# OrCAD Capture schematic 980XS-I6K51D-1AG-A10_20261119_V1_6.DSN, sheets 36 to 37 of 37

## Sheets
36 P0062_S6_USB/AUD/FLASH/XTAL: size A1
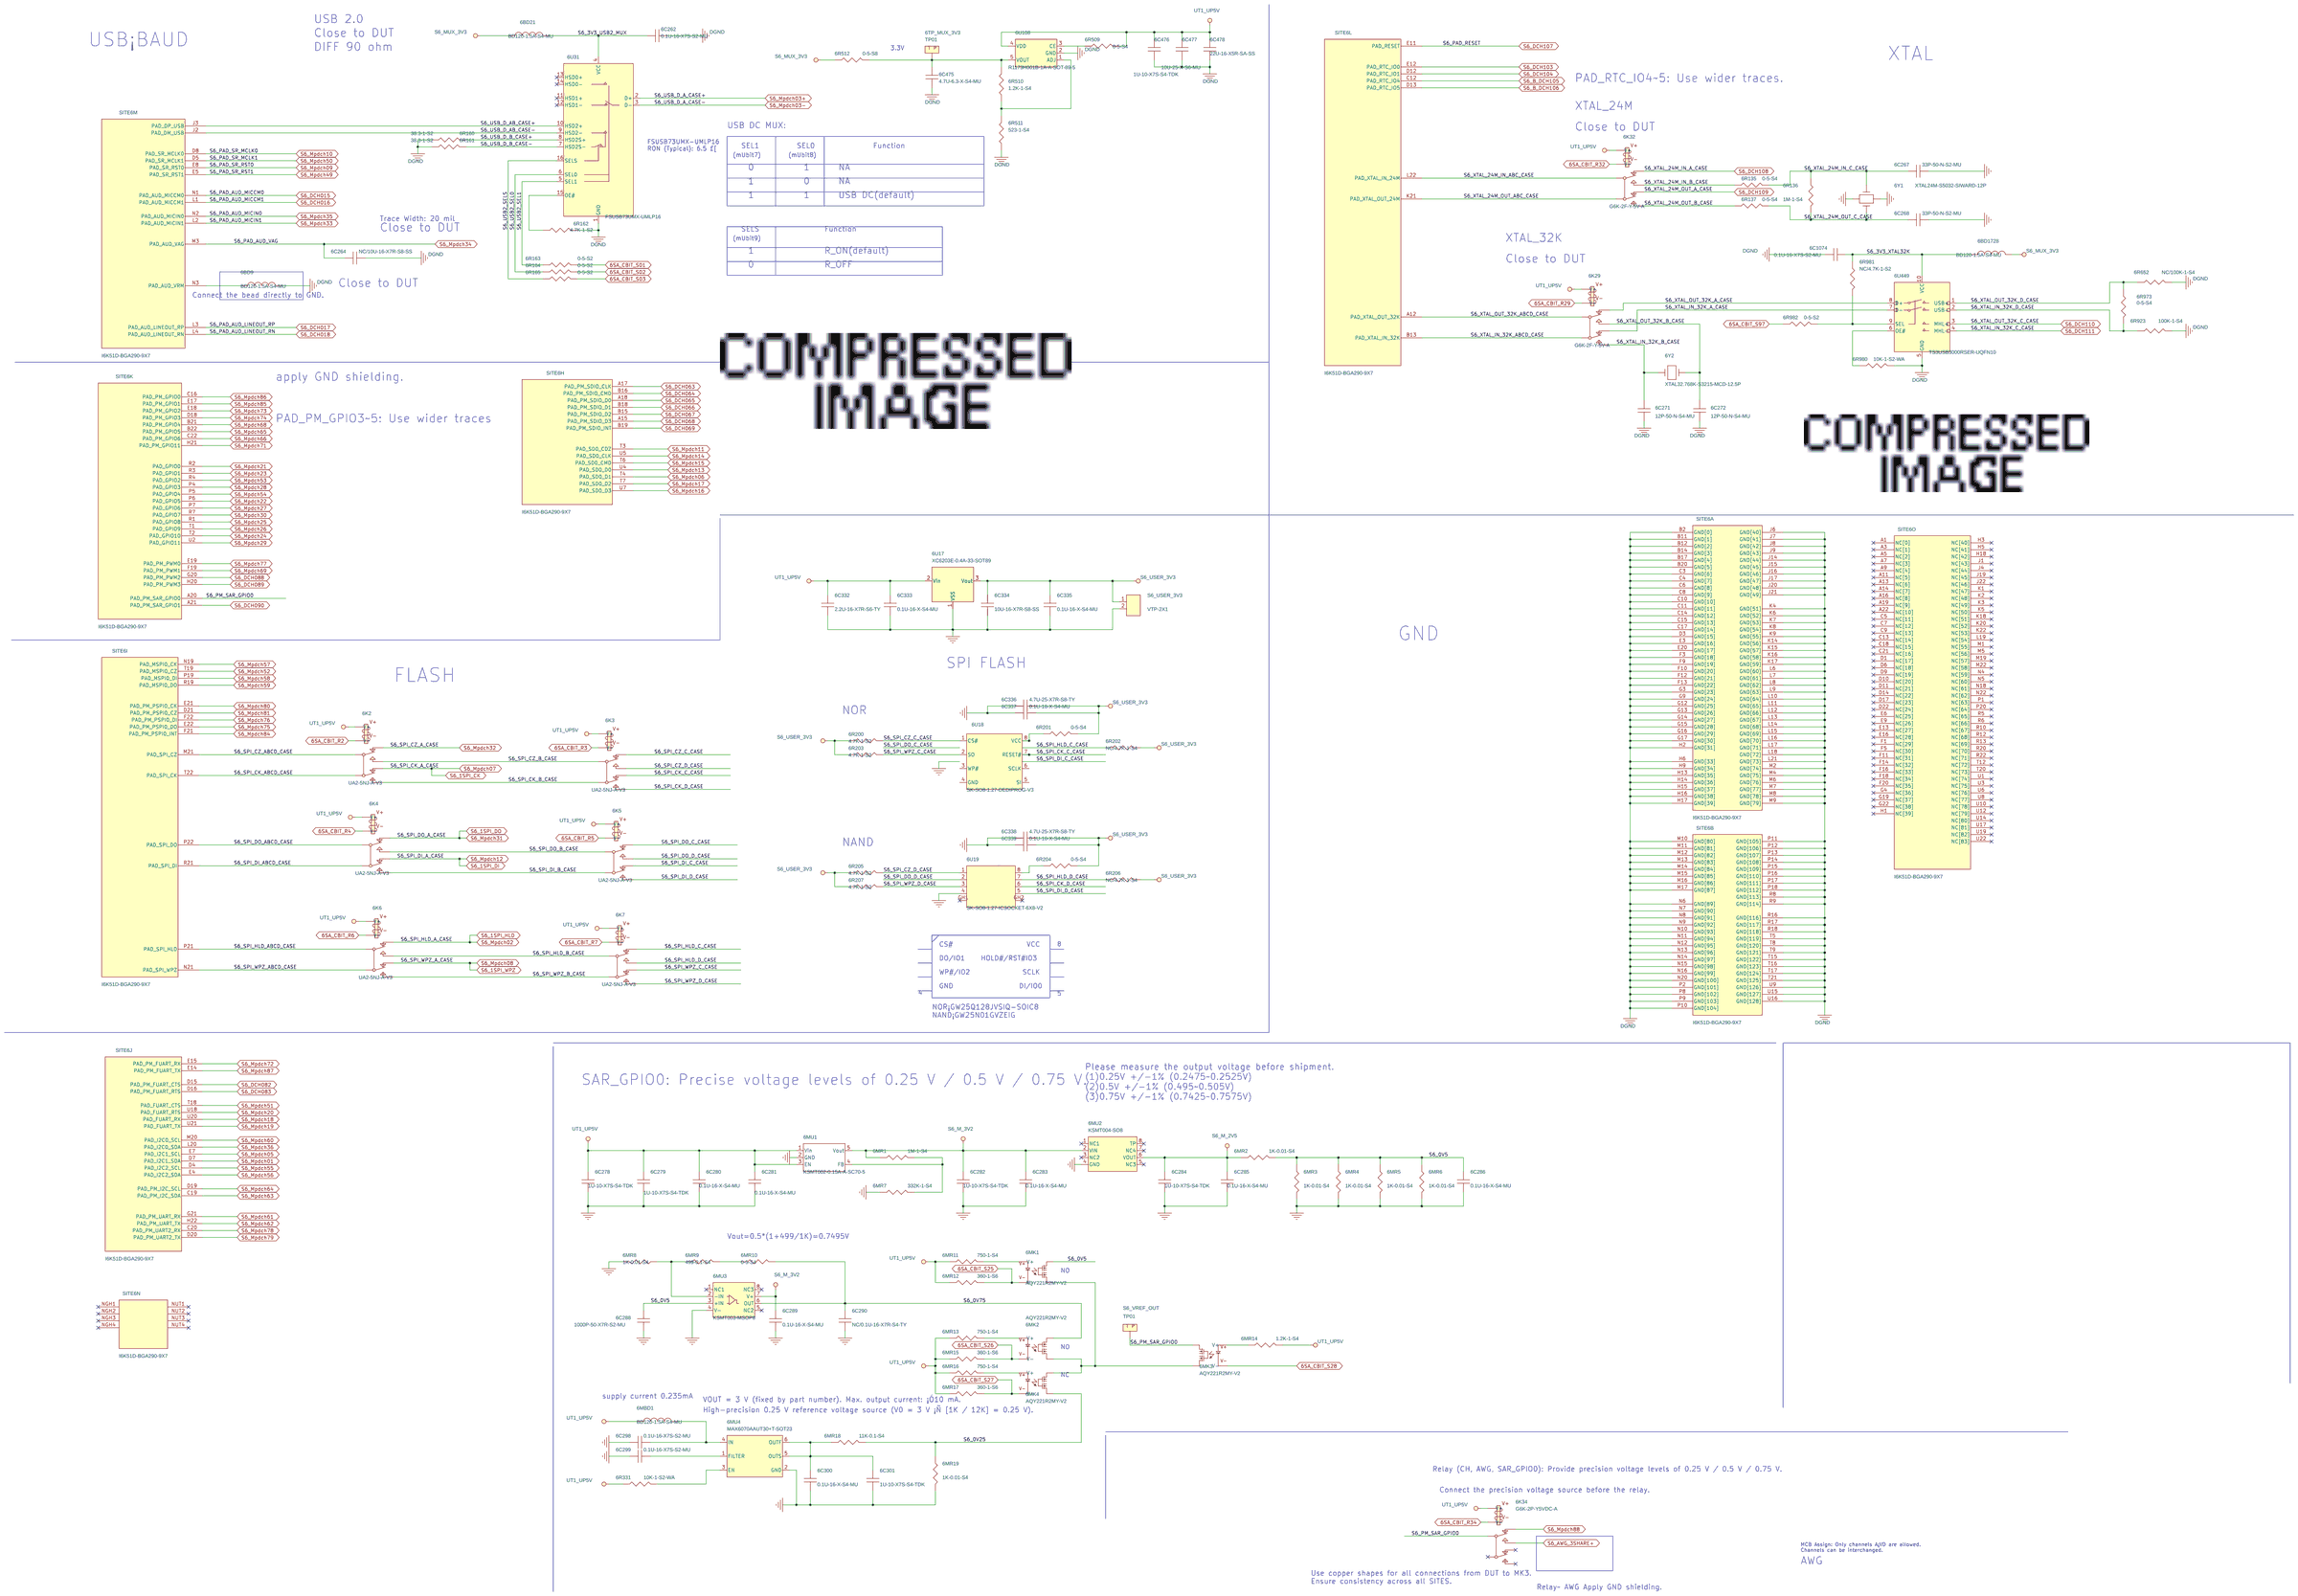
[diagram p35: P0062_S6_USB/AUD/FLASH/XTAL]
37 P0082_S8_USB/AUD/FLASH/XTAL: size A1
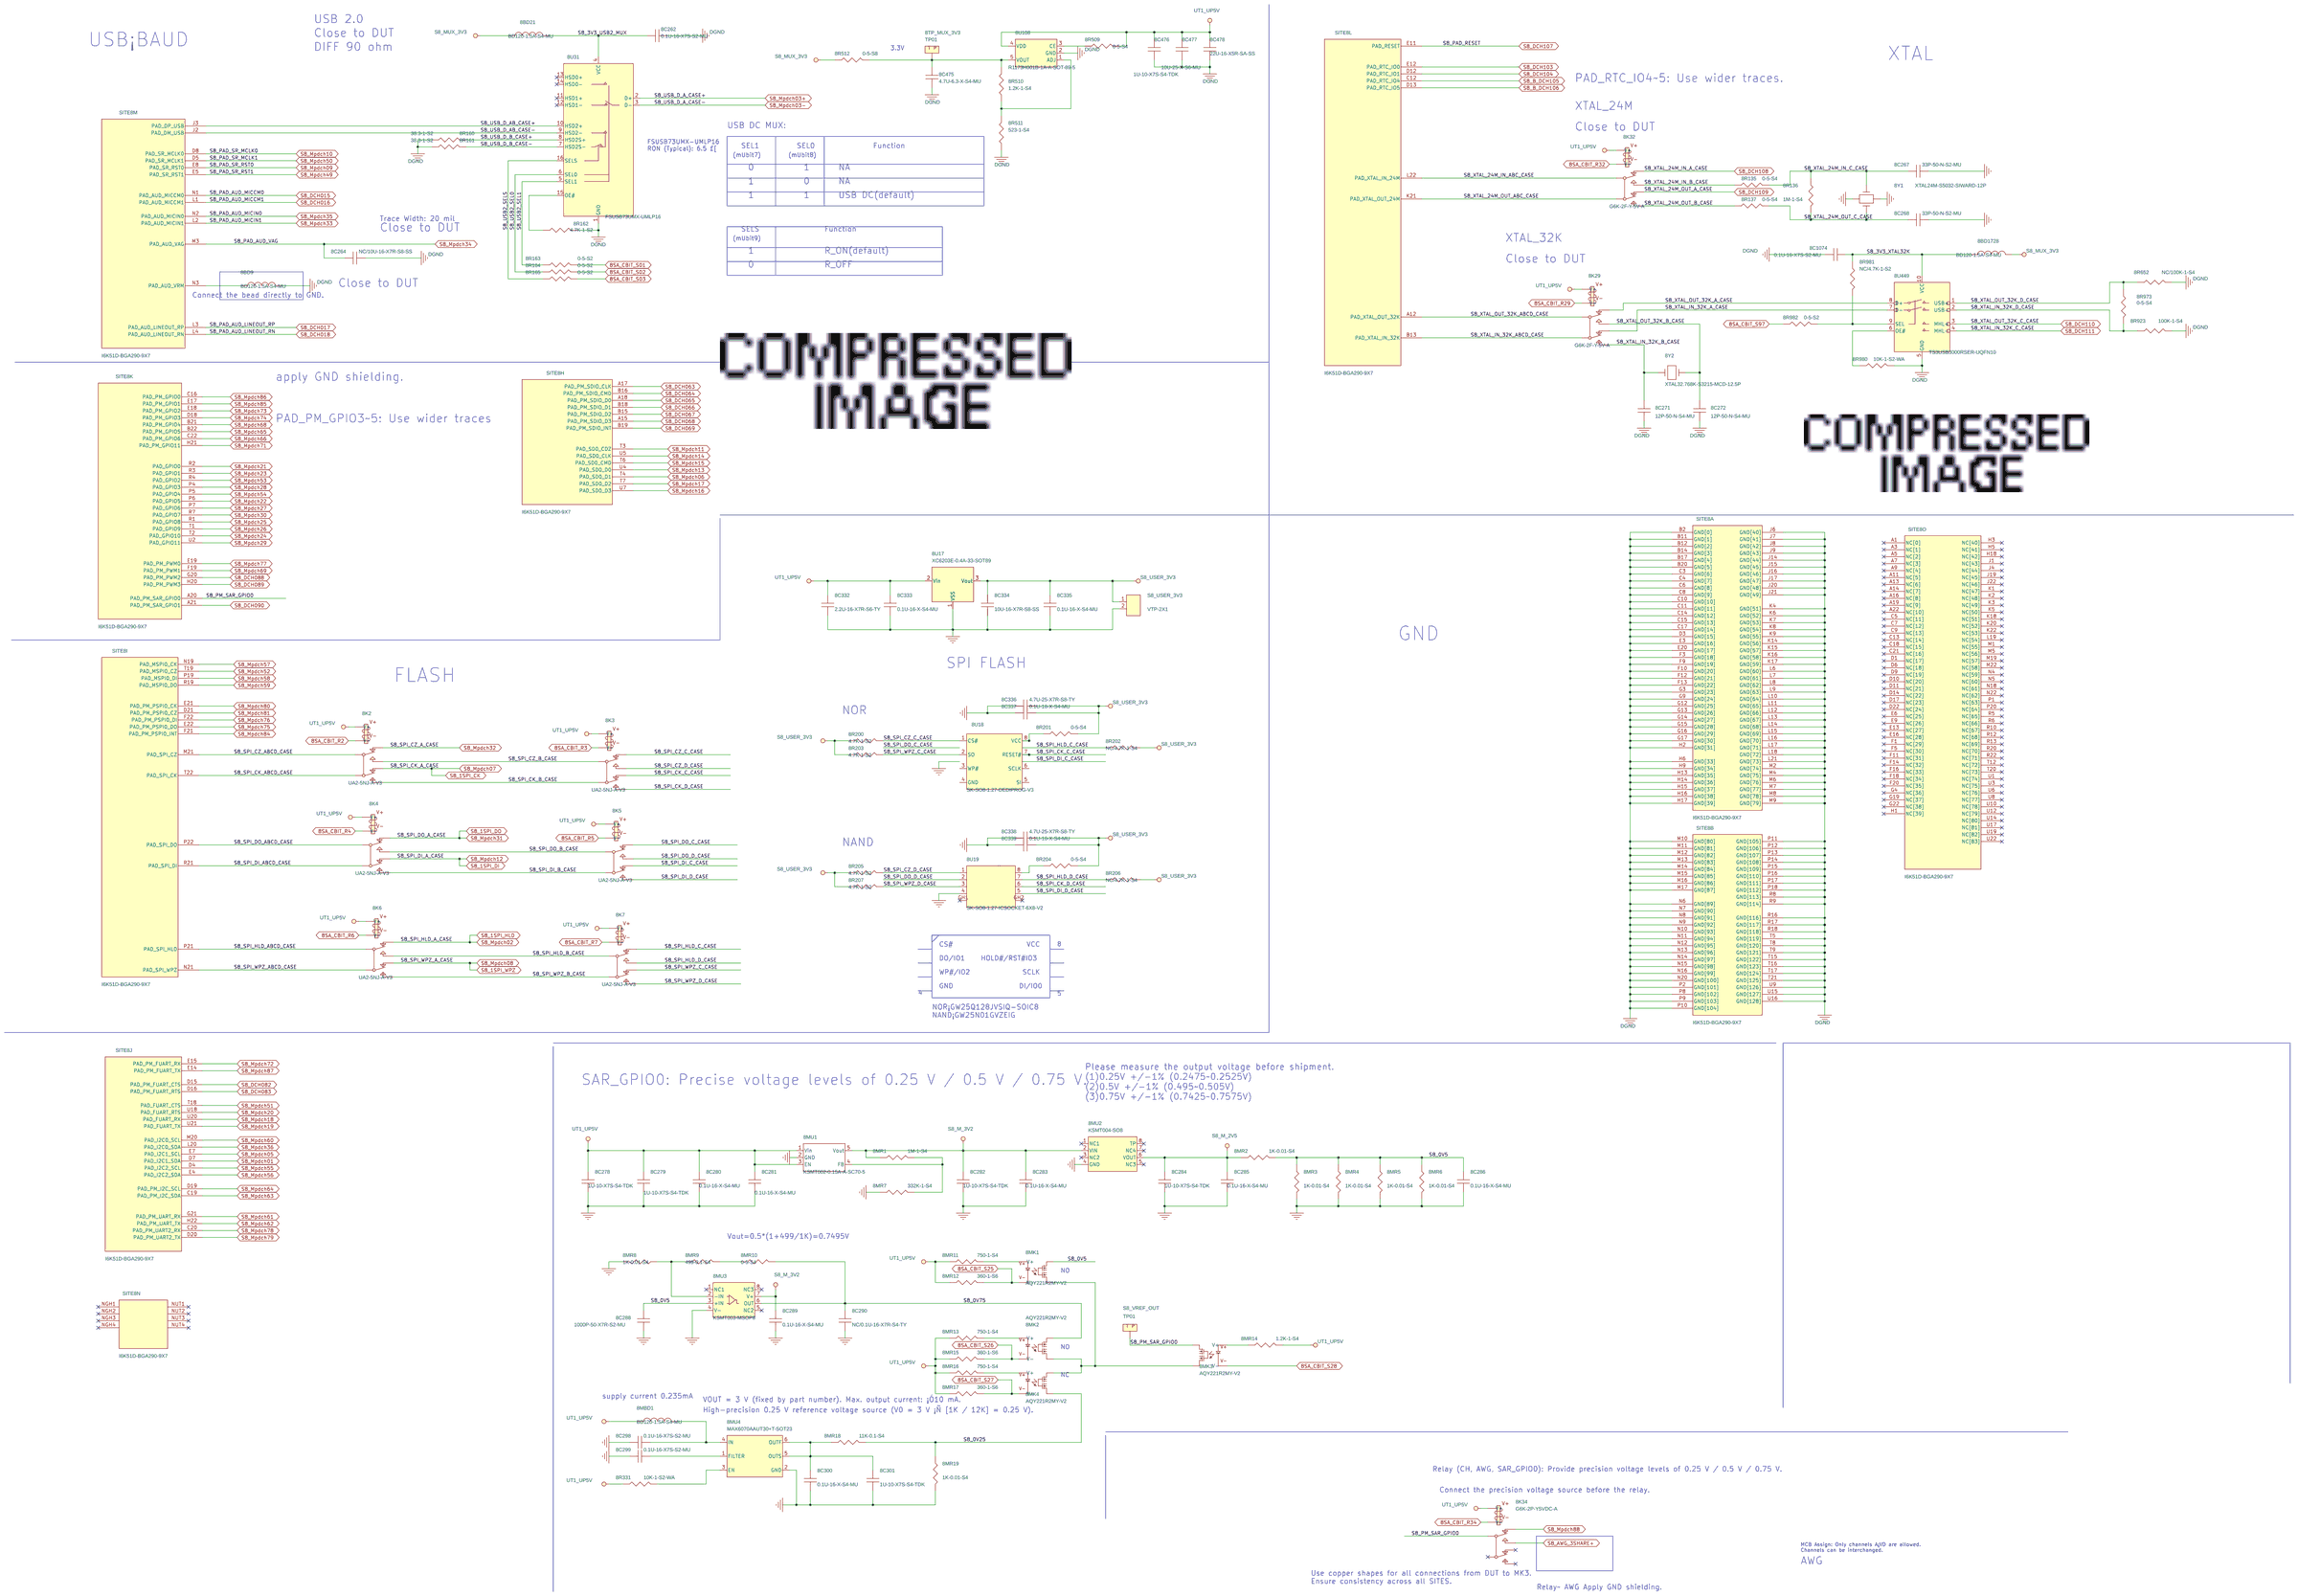
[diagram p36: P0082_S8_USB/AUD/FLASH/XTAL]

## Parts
sheet P0062_S6_USB/AUD/FLASH/XTAL
6BD9  BD120-1.5A-S4-MU  [FB0402]
6BD21  BD120-1.5A-S4-MU  [FB0402]
6BD1728  BD120-1.5A-S4-MU  [FB0402]
6C262  0.1U-16-X7S-S2-MU  [C0201]
6C264  NC/10U-16-X7R-S8-SS  [C0805]
6C267  33P-50-N-S2-MU  [C0201]
6C268  33P-50-N-S2-MU  [C0201]
6C271  12P-50-N-S4-MU  [C0402]
6C272  12P-50-N-S4-MU  [C0402]
6C278  1U-10-X7S-S4-TDK  [C0402]
6C279  1U-10-X7S-S4-TDK  [C0402]
6C280  0.1U-16-X-S4-MU  [C0402]
6C281  0.1U-16-X-S4-MU  [C0402]
6C282  1U-10-X7S-S4-TDK  [C0402]
6C283  0.1U-16-X-S4-MU  [C0402]
6C284  1U-10-X7S-S4-TDK  [C0402]
6C285  0.1U-16-X-S4-MU  [C0402]
6C286  0.1U-16-X-S4-MU  [C0402]
6C288  1000P-50-X7R-S2-MU  [C0201]
6C289  0.1U-16-X-S4-MU  [C0402]
6C290  NC/0.1U-16-X7R-S4-TY  [C0402]
6C298  0.1U-16-X7S-S2-MU  [C0201]
6C299  0.1U-16-X7S-S2-MU  [C0201]
6C300  0.1U-16-X-S4-MU  [C0402]
6C301  1U-10-X7S-S4-TDK  [C0402]
6C332  2.2U-16-X7R-S6-TY  [C0603]
6C333  0.1U-16-X-S4-MU  [C0402]
6C334  10U-16-X7R-S8-SS  [C0805]
6C335  0.1U-16-X-S4-MU  [C0402]
6C336  4.7U-25-X7R-S8-TY  [C0805]
6C337  0.1U-16-X-S4-MU  [C0402]
6C338  4.7U-25-X7R-S8-TY  [C0805]
6C339  0.1U-16-X-S4-MU  [C0402]
6C475  4.7U-6.3-X-S4-MU  [C0402]
6C476  1U-10-X7S-S4-TDK  [C0402]
6C477  10U-25-X-S6-MU  [C0603]
6C478  22U-16-X5R-SA-SS  [C1206]
6C1074  0.1U-16-X7S-S2-MU  [C0201_MINI]
6K2  UA2-5NJ-A-V3  [RL_NECUA2_5V_V3]
6K3  UA2-5NJ-A-V3  [RL_NECUA2_5V_V3]
6K4  UA2-5NJ-A-V3  [RL_NECUA2_5V_V3]
6K5  UA2-5NJ-A-V3  [RL_NECUA2_5V_V3]
6K6  UA2-5NJ-A-V3  [RL_NECUA2_5V_V3]
6K7  UA2-5NJ-A-V3  [RL_NECUA2_5V_V3]
6K29  G6K-2F-Y-5V-A  [RL_G6K2F-Y_5V_OMRON]
6K32  G6K-2F-Y-5V-A  [RL_G6K2F-Y_5V_OMRON]
6K34  G6K-2P-Y5VDC-A  [RL_OMRONG6K2PY_5V]
6MBD1  BD120-1.5A-S4-MU  [FB0402]
6MK1  AQY221R2MY-V2  [RL_AQY221R2MY_5V_V2]
6MK2  AQY221R2MY-V2  [RL_AQY221R2MY_5V_V2]
6MK3  AQY221R2MY-V2  [RL_AQY221R2MY_5V_V2]
6MK4  AQY221R2MY-V2  [RL_AQY221R2MY_5V_V2]
6MR1  1M-1-S4  [R0402_UNBGA_V2]
6MR2  1K-0.01-S4  [R0402_UNBGA_V2]
6MR3  1K-0.01-S4  [R0402_UNBGA_V2]
6MR4  1K-0.01-S4  [R0402_UNBGA_V2]
6MR5  1K-0.01-S4  [R0402_UNBGA_V2]
6MR6  1K-0.01-S4  [R0402_UNBGA_V2]
6MR7  332K-1-S4  [R0402_UNBGA_V2]
6MR8  1K-0.01-S4  [R0402_UNBGA_V2]
6MR9  499-0.1-S4  [R0402]
6MR10  0-5-S4  [R0402]
6MR11  750-1-S4  [R0402]
6MR12  360-1-S6  [R0603]
6MR13  750-1-S4  [R0402]
6MR14  1.2K-1-S4  [R0402]
6MR15  360-1-S6  [R0603]
6MR16  750-1-S4  [R0402]
6MR17  360-1-S6  [R0603]
6MR18  11K-0.1-S4  [R0402]
6MR19  1K-0.01-S4  [R0402_UNBGA_V2]
6MU1  KSMT002-0.15A-A-SC70-5  [SC70_5P]
6MU2  KSMT004-SO8  [SO8_244X127MM]
6MU3  KSMT003-MSOP8  [SO8_172X0P65MM]
6MU4  MAX6070AAUT30+T-SOT23  [SOT23_6P_0P95X2P7MM_H1P45MM]
6R135  0-5-S4  [R0402]
6R136  1M-1-S4  [R0402]
6R137  0-5-S4  [R0402]
6R160  38.3-1-S2  [R0201_MINI]
6R161  38.3-1-S2  [R0201_MINI]
6R162  4.7K-1-S2  [R0201_MINI]
6R163  0-5-S2  [R0201_MINI]
6R164  0-5-S2  [R0201_MINI]
6R165  0-5-S2  [R0201_MINI]
6R200  4.7K-1-S2  [R0201]
6R201  0-5-S4  [R0402]
6R202  NC/4.7K-1-S4  [R0402]
6R203  4.7K-1-S2  [R0201]
6R204  0-5-S4  [R0402]
6R205  4.7K-1-S2  [R0201]
6R206  NC/4.7K-1-S4  [R0402]
6R207  4.7K-1-S2  [R0201]
6R331  10K-1-S2-WA  [R0201]
6R509  0-5-S4  [R0402]
6R510  1.2K-1-S4  [R0402]
6R511  523-1-S4  [R0402]
6R512  0-5-S8  [R0805]
6R652  NC/100K-1-S4  [R0402]
6R923  100K-1-S4  [R0402]
6R973  0-5-S4  [R0402]
6R980  10K-1-S2-WA  [R0201]
6R981  NC/4.7K-1-S2  [R0201]
6R982  0-5-S2  [R0201]
6TP_MUX_3V3  TP01  [TP_040_T]
6U17  XC6203E-0.4A-33-SOT89  [SOT89]
6U18  SK-SO8-1.27-DEDIPROG-V3  [SK_SO8_1P27MM_DEDIPROG_V3]
6U19  SK-SO8-1.27-ICSOCKET-6X8-V2  [SK_SO8_1P27MM_SDQ54CBAA_V2]
6U31  FSUSB73UMX-UMLP16  [SW_UMLP2P6X1P8_12P_0P4MM]
6U108  R1173H001B-1A-A-SOT-89-5  [SOT_89_5]
6U449  TS3USB3000RSER-UQFN10  [UQFN2P05X1P55_10P_0P5MM]
6Y1  XTAL24M-S5032-SIWARD-12P  [XTAL_S_DUAL1]
6Y2  XTAL32.768K-S3215-MCD-12.5P  [XTAL_3P2X1P5MM_2P_MC]
S6_USER_3V3  VTP-2X1  [VTP_2P_100]
S6_VREF_OUT  TP01  [TP_040_T]
SITE6  I6K51D-BGA290-9X7  [SK_TFBGA7X9_290P_0P4MM_JG]  (sections A,B,C,D,E,F,G,H,I,J,K,L,M,N,O)
sheet P0082_S8_USB/AUD/FLASH/XTAL
8BD9  BD120-1.5A-S4-MU  [FB0402]
8BD21  BD120-1.5A-S4-MU  [FB0402]
8BD1728  BD120-1.5A-S4-MU  [FB0402]
8C262  0.1U-16-X7S-S2-MU  [C0201]
8C264  NC/10U-16-X7R-S8-SS  [C0805]
8C267  33P-50-N-S2-MU  [C0201]
8C268  33P-50-N-S2-MU  [C0201]
8C271  12P-50-N-S4-MU  [C0402]
8C272  12P-50-N-S4-MU  [C0402]
8C278  1U-10-X7S-S4-TDK  [C0402]
8C279  1U-10-X7S-S4-TDK  [C0402]
8C280  0.1U-16-X-S4-MU  [C0402]
8C281  0.1U-16-X-S4-MU  [C0402]
8C282  1U-10-X7S-S4-TDK  [C0402]
8C283  0.1U-16-X-S4-MU  [C0402]
8C284  1U-10-X7S-S4-TDK  [C0402]
8C285  0.1U-16-X-S4-MU  [C0402]
8C286  0.1U-16-X-S4-MU  [C0402]
8C288  1000P-50-X7R-S2-MU  [C0201]
8C289  0.1U-16-X-S4-MU  [C0402]
8C290  NC/0.1U-16-X7R-S4-TY  [C0402]
8C298  0.1U-16-X7S-S2-MU  [C0201]
8C299  0.1U-16-X7S-S2-MU  [C0201]
8C300  0.1U-16-X-S4-MU  [C0402]
8C301  1U-10-X7S-S4-TDK  [C0402]
8C332  2.2U-16-X7R-S6-TY  [C0603]
8C333  0.1U-16-X-S4-MU  [C0402]
8C334  10U-16-X7R-S8-SS  [C0805]
8C335  0.1U-16-X-S4-MU  [C0402]
8C336  4.7U-25-X7R-S8-TY  [C0805]
8C337  0.1U-16-X-S4-MU  [C0402]
8C338  4.7U-25-X7R-S8-TY  [C0805]
8C339  0.1U-16-X-S4-MU  [C0402]
8C475  4.7U-6.3-X-S4-MU  [C0402]
8C476  1U-10-X7S-S4-TDK  [C0402]
8C477  10U-25-X-S6-MU  [C0603]
8C478  22U-16-X5R-SA-SS  [C1206]
8C1074  0.1U-16-X7S-S2-MU  [C0201_MINI]
8K2  UA2-5NJ-A-V3  [RL_NECUA2_5V_V3]
8K3  UA2-5NJ-A-V3  [RL_NECUA2_5V_V3]
8K4  UA2-5NJ-A-V3  [RL_NECUA2_5V_V3]
8K5  UA2-5NJ-A-V3  [RL_NECUA2_5V_V3]
8K6  UA2-5NJ-A-V3  [RL_NECUA2_5V_V3]
8K7  UA2-5NJ-A-V3  [RL_NECUA2_5V_V3]
8K29  G6K-2F-Y-5V-A  [RL_G6K2F-Y_5V_OMRON]
8K32  G6K-2F-Y-5V-A  [RL_G6K2F-Y_5V_OMRON]
8K34  G6K-2P-Y5VDC-A  [RL_OMRONG6K2PY_5V]
8MBD1  BD120-1.5A-S4-MU  [FB0402]
8MK1  AQY221R2MY-V2  [RL_AQY221R2MY_5V_V2]
8MK2  AQY221R2MY-V2  [RL_AQY221R2MY_5V_V2]
8MK3  AQY221R2MY-V2  [RL_AQY221R2MY_5V_V2]
8MK4  AQY221R2MY-V2  [RL_AQY221R2MY_5V_V2]
8MR1  1M-1-S4  [R0402_UNBGA_V2]
8MR2  1K-0.01-S4  [R0402_UNBGA_V2]
8MR3  1K-0.01-S4  [R0402_UNBGA_V2]
8MR4  1K-0.01-S4  [R0402_UNBGA_V2]
8MR5  1K-0.01-S4  [R0402_UNBGA_V2]
8MR6  1K-0.01-S4  [R0402_UNBGA_V2]
8MR7  332K-1-S4  [R0402_UNBGA_V2]
8MR8  1K-0.01-S4  [R0402_UNBGA_V2]
8MR9  499-0.1-S4  [R0402]
8MR10  0-5-S4  [R0402]
8MR11  750-1-S4  [R0402]
8MR12  360-1-S6  [R0603]
8MR13  750-1-S4  [R0402]
8MR14  1.2K-1-S4  [R0402]
8MR15  360-1-S6  [R0603]
8MR16  750-1-S4  [R0402]
8MR17  360-1-S6  [R0603]
8MR18  11K-0.1-S4  [R0402]
8MR19  1K-0.01-S4  [R0402_UNBGA_V2]
8MU1  KSMT002-0.15A-A-SC70-5  [SC70_5P]
8MU2  KSMT004-SO8  [SO8_244X127MM]
8MU3  KSMT003-MSOP8  [SO8_172X0P65MM]
8MU4  MAX6070AAUT30+T-SOT23  [SOT23_6P_0P95X2P7MM_H1P45MM]
8R135  0-5-S4  [R0402]
8R136  1M-1-S4  [R0402]
8R137  0-5-S4  [R0402]
8R160  38.3-1-S2  [R0201_MINI]
8R161  38.3-1-S2  [R0201_MINI]
8R162  4.7K-1-S2  [R0201_MINI]
8R163  0-5-S2  [R0201_MINI]
8R164  0-5-S2  [R0201_MINI]
8R165  0-5-S2  [R0201_MINI]
8R200  4.7K-1-S2  [R0201]
8R201  0-5-S4  [R0402]
8R202  NC/4.7K-1-S4  [R0402]
8R203  4.7K-1-S2  [R0201]
8R204  0-5-S4  [R0402]
8R205  4.7K-1-S2  [R0201]
8R206  NC/4.7K-1-S4  [R0402]
8R207  4.7K-1-S2  [R0201]
8R331  10K-1-S2-WA  [R0201]
8R509  0-5-S4  [R0402]
8R510  1.2K-1-S4  [R0402]
8R511  523-1-S4  [R0402]
8R512  0-5-S8  [R0805]
8R652  NC/100K-1-S4  [R0402]
8R923  100K-1-S4  [R0402]
8R973  0-5-S4  [R0402]
8R980  10K-1-S2-WA  [R0201]
8R981  NC/4.7K-1-S2  [R0201]
8R982  0-5-S2  [R0201]
8TP_MUX_3V3  TP01  [TP_040_T]
8U17  XC6203E-0.4A-33-SOT89  [SOT89]
8U18  SK-SO8-1.27-DEDIPROG-V3  [SK_SO8_1P27MM_DEDIPROG_V3]
8U19  SK-SO8-1.27-ICSOCKET-6X8-V2  [SK_SO8_1P27MM_SDQ54CBAA_V2]
8U31  FSUSB73UMX-UMLP16  [SW_UMLP2P6X1P8_12P_0P4MM]
8U108  R1173H001B-1A-A-SOT-89-5  [SOT_89_5]
8U449  TS3USB3000RSER-UQFN10  [UQFN2P05X1P55_10P_0P5MM]
8Y1  XTAL24M-S5032-SIWARD-12P  [XTAL_S_DUAL1]
8Y2  XTAL32.768K-S3215-MCD-12.5P  [XTAL_3P2X1P5MM_2P_MC]
S8_USER_3V3  VTP-2X1  [VTP_2P_100]
S8_VREF_OUT  TP01  [TP_040_T]
sheet P0083_S8_MIPI
SITE8  I6K51D-BGA290-9X7  [SK_TFBGA7X9_290P_0P4MM_JG]  (sections A,B,C,D,E,F,G,H,I,J,K,L,M,N,O)

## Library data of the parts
6BD9 8BD9 = BD120-1.5A-S4-MU: KAIROSNAME: BD9
6BD21 6BD1728 8BD21 8BD1728 = BD120-1.5A-S4-MU: KAIROSNAME: BD21
6C262 8C262 = 0.1U-16-X7S-S2-MU
6C264 8C264 = 10U-16-X7R-S8-SS: KAIROSNAME: C264
6C267 8C267 = 33P-50-N-S2-MU: KAIROSNAME: C267
6C268 8C268 = 33P-50-N-S2-MU: KAIROSNAME: C268
6C271 8C271 = 12P-50-N-S4-MU: KAIROSNAME: C271
6C272 8C272 = 12P-50-N-S4-MU: KAIROSNAME: C272
6C278 8C278 = 1U-10-X7S-S4-TDK: KAIROSNAME: C278
6C279 8C279 = 1U-10-X7S-S4-TDK: KAIROSNAME: C279
6C280 8C280 = 0.1U-16-X-S4-MU: KAIROSNAME: C280
6C281 8C281 = 0.1U-16-X-S4-MU: KAIROSNAME: C281
6C282 8C282 = 1U-10-X7S-S4-TDK: KAIROSNAME: C282
6C283 8C283 = 0.1U-16-X-S4-MU: KAIROSNAME: C283
6C284 8C284 = 1U-10-X7S-S4-TDK: KAIROSNAME: C284
6C285 8C285 = 0.1U-16-X-S4-MU: KAIROSNAME: C285
6C286 8C286 = 0.1U-16-X-S4-MU: KAIROSNAME: C286
6C288 8C288 = 1000P-50-X7R-S2-MU: KAIROSNAME: C288
6C289 8C289 = 0.1U-16-X-S4-MU: KAIROSNAME: C289
6C290 8C290 = 0.1U-16-X-S4-MU: KAIROSNAME: C290
6C298 8C298 = 0.1U-16-X7S-S2-MU: KAIROSNAME: C298
6C299 8C299 = 0.1U-16-X7S-S2-MU: KAIROSNAME: C299
6C300 8C300 = 0.1U-16-X-S4-MU: KAIROSNAME: C300
6C301 8C301 = 1U-10-X7S-S4-TDK: KAIROSNAME: C301
6C332 8C332 = 2.2U-16-X7R-S6-TY
6C333 6C335 6C337 6C339 8C333 8C335 8C337 8C339 = 0.1U-16-X-S4-MU
6C334 8C334 = 10U-16-X7R-S8-SS
6C336 6C338 8C336 8C338 = 4.7U-25-X7R-S8-TY
6C475 8C475 = 4.7U-6.3-X-S4-MU: KAIROSNAME: C475
6C476 8C476 = 1U-10-X-S4-MU: KAIROSNAME: C476
6C477 8C477 = 10U-25-X-S6-MU: KAIROSNAME: C477
6C478 8C478 = 22U-16-X5R-SA-SS: KAIROSNAME: C478
6C1074 8C1074 = 0.1U-16-X7S-S2-MU: KAIROSNAME: C262
6K2-6K7 8K2-8K7 = UA2-5NJ-A-V3
6K29 8K29 = G6K-2F-Y-5V-A: KAIROSNAME: K29
6K32 8K32 = G6K-2F-Y-5V-A: KAIROSNAME: K32
6K34 8K34 = G6K-2P-Y5VDC-A: KAIROSNAME: K34
6MBD1 8MBD1 = BD120-1.5A-S4-MU: KAIROSNAME: MBD1
6MK1 8MK1 = AQY221R2MY-V2: KAIROSNAME: MK1
6MK2 8MK2 = AQY221R2MY-V2: KAIROSNAME: MK2
6MK3 8MK3 = AQY221R2MY-V2: KAIROSNAME: MK3
6MK4 8MK4 = AQY221R2MY-V2: KAIROSNAME: MK4
6MR1 8MR1 = 1M-1-S4: KAIROSNAME: MR1
6MR2 8MR2 = 1K-0.01-S4: KAIROSNAME: MR2
6MR3 8MR3 = 1K-0.01-S4: KAIROSNAME: MR3
6MR4 8MR4 = 1K-0.01-S4: KAIROSNAME: MR4
6MR5 8MR5 = 1K-0.01-S4: KAIROSNAME: MR5
6MR6 8MR6 = 1K-0.01-S4: KAIROSNAME: MR6
6MR7 8MR7 = 332K-1-S4: KAIROSNAME: MR7
6MR8 8MR8 = 1K-0.01-S4: KAIROSNAME: MR8
6MR9 8MR9 = 499-0.1-S4: KAIROSNAME: MR9
6MR10 8MR10 = 0-5-S4: KAIROSNAME: MR10
6MR11 8MR11 = 750-1-S4: KAIROSNAME: MR11
6MR12 8MR12 = 360-1-S4: KAIROSNAME: MR12
6MR13 8MR13 = 750-1-S4: KAIROSNAME: MR13
6MR14 8MR14 = 1.2K-1-S4: KAIROSNAME: MR14
6MR15 8MR15 = 360-1-S4: KAIROSNAME: MR15
6MR16 8MR16 = 750-1-S4: KAIROSNAME: MR16
6MR17 8MR17 = 360-1-S4: KAIROSNAME: MR17
6MR18 8MR18 = 11K-0.1-S4: KAIROSNAME: MR18
6MR19 8MR19 = 1K-0.01-S4: KAIROSNAME: MR19
6MU1 8MU1 = KSMT002-0.15A-A-SC70-5: KAIROSNAME: MU1
6MU2 8MU2 = KSMT004-SO8: KAIROSNAME: MU2
6MU3 8MU3 = KSMT003-MSOP8: KAIROSNAME: MU3
6MU4 8MU4 = MAX6070AAUT30+T-SOT23: KAIROSNAME: MU4
6R135 8R135 = 0-5-S4: KAIROSNAME: R135
6R136 8R136 = 1M-1-S4: KAIROSNAME: R136
6R137 8R137 = 0-5-S4: KAIROSNAME: R137
6R160 8R160 = 38.3-1-S2: KAIROSNAME: R160
6R161 8R161 = 38.3-1-S2: KAIROSNAME: R161
6R162 8R162 = 4.7K-1-S2: KAIROSNAME: R162
6R163 8R163 = 0-5-S2: KAIROSNAME: R163
6R164 8R164 = 0-5-S2: KAIROSNAME: R164
6R165 8R165 = 0-5-S2: KAIROSNAME: R165
6R200 6R202 6R203 6R205-6R207 6R981 8R200 8R202 8R203 8R205-8R207 8R981 = 4.7K-1-S2
6R201 6R204 6R973 8R201 8R204 8R973 = 0-5-S4
6R331 8R331 = 10K-1-S2-WA: KAIROSNAME: R331
6R509 8R509 = 0-5-S4: KAIROSNAME: R509
6R510 8R510 = 1.2K-1-S4: KAIROSNAME: R510
6R511 8R511 = 523-1-S4: KAIROSNAME: R511
6R512 8R512 = 0-5-S8: KAIROSNAME: R512
6R652 6R923 8R652 8R923 = 100K-1-S4
6R980 8R980 = 10K-1-S2-WA
6R982 8R982 = 0-5-S2
6TP_MUX_3V3 8TP_MUX_3V3 = TP03-D: KAIROSNAME: TP_MUX_3V3
6U17 8U17 = XC6203E-0.4A-33-SOT89
6U18 8U18 = SK-SO8-1.27-DEDIPROG-V3
6U19 8U19 = SK-SO8-1.27-ICSOCKET-6X8-V2
6U31 8U31 = FSUSB73UMX-UMLP16: KAIROSNAME: U31
6U108 8U108 = R1173H001B-1A-A-SOT-89-5: KAIROSNAME: U108
6U449 8U449 = TS3USB3000RSER-UQFN10
6Y1 8Y1 = XTAL24M-S5032-SIWARD-12P: KAIROSNAME: Y1
6Y2 8Y2 = XTAL32.768K-S3215-MCD-12.5P: KAIROSNAME: Y2
S6_USER_3V3 S8_USER_3V3 = VTP-2X1
S6_VREF_OUT S8_VREF_OUT = TP01: KAIROSNAME: S1_VREF_OUT
SITE6 SITE8 = I6K51D-BGA290-9X7

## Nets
DGND: 6BD9.2 6C262.2 6C264.2 6C267.2 6C268.2 6C271.2 6C272.2 6C278.2 6C279.2 6C280.2 6C281.2 6C282.2 6C283.2 6C284.2 6C285.2 6C286.2 6C288.2 6C289.2 6C290.2 6C298.1 6C299.1 6C300.2 6C301.2 6C332.2 6C333.2 6C334.2 6C335.2 6C336.1 6C337.1 6C338.1 6C339.1 6C475.2 6C476.2 6C477.2 6C478.2 6C1074.2 6MR3.2 6MR4.2 6MR5.2 6MR6.2 6MR7.1 6MR8.2 6MR19.2 6MU1.2(GND) 6MU2.4(GND) 6MU3.4(V-) 6MU4.2(GND) 6R160.1 6R161.1 6R162.2 6R511.2 6R652.2 6R923.2 6R980.2 6U17.1(VSS) 6U19.4 6U31.1(GND) 6U108.2(GND) 6U449.5(GND) 6Y1.2 6Y1.4 8BD9.2 8C262.2 8C264.2 8C267.2 8C268.2 8C271.2 8C272.2 8C278.2 8C279.2 8C280.2 8C281.2 8C282.2 8C283.2 8C284.2 8C285.2 8C286.2 8C288.2 8C289.2 8C290.2 8C298.1 8C299.1 8C300.2 8C301.2 8C332.2 8C333.2 8C334.2 8C335.2 8C336.1 8C337.1 8C338.1 8C339.1 8C475.2 8C476.2 8C477.2 8C478.2 8C1074.2 8MR3.2 8MR4.2 8MR5.2 8MR6.2 8MR7.1 8MR8.2 8MR19.2 8MU1.2(GND) 8MU2.4(GND) 8MU3.4(V-) 8MU4.2(GND) 8R160.1 8R161.1 8R162.2 8R511.2 8R652.2 8R923.2 8R980.2 8U17.1(VSS) 8U19.4 8U31.1(GND) 8U108.2(GND) 8U449.5(GND) 8Y1.2 8Y1.4 S6_USER_3V3.2 S8_USER_3V3.2 SITE6.B2(GND[0]) SITE6.B11(GND[1]) SITE6.B12(GND[2]) SITE6.B14(GND[3]) SITE6.B17(GND[4]) SITE6.B20(GND[5]) SITE6.C3(GND[6]) SITE6.C4(GND[7]) SITE6.C6(GND[8]) SITE6.C8(GND[9]) SITE6.C10(GND[10]) SITE6.C11(GND[11]) SITE6.C14(GND[12]) SITE6.C15(GND[13]) SITE6.C17(GND[14]) SITE6.D3(GND[15]) SITE6.E3(GND[16]) SITE6.E20(GND[17]) SITE6.F3(GND[18]) SITE6.F9(GND[19]) SITE6.F10(GND[20]) SITE6.F12(GND[21]) SITE6.F13(GND[22]) SITE6.G3(GND[23]) SITE6.G9(GND[24]) SITE6.G12(GND[25]) SITE6.G13(GND[26]) SITE6.G14(GND[27]) SITE6.G15(GND[28]) SITE6.G16(GND[29]) SITE6.G17(GND[30]) SITE6.H2(GND[31]) SITE6.H6(GND[33]) SITE6.H9(GND[34]) SITE6.H13(GND[35]) SITE6.H14(GND[36]) SITE6.H15(GND[37]) SITE6.H16(GND[38]) SITE6.H17(GND[39]) SITE6.J6(GND[40]) SITE6.J7(GND[41]) SITE6.J8(GND[42]) SITE6.J9(GND[43]) SITE6.J14(GND[44]) SITE6.J15(GND[45]) SITE6.J16(GND[46]) SITE6.J17(GND[47]) SITE6.J20(GND[48]) SITE6.J21(GND[49]) SITE6.K4(GND[51]) SITE6.K6(GND[52]) SITE6.K7(GND[53]) SITE6.K8(GND[54]) SITE6.K9(GND[55]) SITE6.K14(GND[56]) SITE6.K15(GND[57]) SITE6.K16(GND[58]) SITE6.K17(GND[59]) SITE6.L6(GND[60]) SITE6.L7(GND[61]) SITE6.L8(GND[62]) SITE6.L9(GND[63]) SITE6.L10(GND[64]) SITE6.L11(GND[65]) SITE6.L12(GND[66]) SITE6.L13(GND[67]) SITE6.L14(GND[68]) SITE6.L15(GND[69]) SITE6.L16(GND[70]) SITE6.L17(GND[71]) SITE6.L18(GND[72]) SITE6.L21(GND[73]) SITE6.M2(GND[74]) SITE6.M4(GND[75]) SITE6.M6(GND[76]) SITE6.M7(GND[77]) SITE6.M8(GND[78]) SITE6.M9(GND[79]) SITE6.M10(GND[80]) SITE6.M11(GND[81]) SITE6.M12(GND[82]) SITE6.M13(GND[83]) SITE6.M14(GND[84]) SITE6.M15(GND[85]) SITE6.M16(GND[86]) SITE6.M17(GND[87]) SITE6.N6(GND[89]) SITE6.N7(GND[90]) SITE6.N8(GND[91]) SITE6.N9(GND[92]) SITE6.N10(GND[93]) SITE6.N11(GND[94]) SITE6.N12(GND[95]) SITE6.N13(GND[96]) SITE6.N14(GND[97]) SITE6.N15(GND[98]) SITE6.N16(GND[99]) SITE6.N20(GND[100]) SITE6.P2(GND[101]) SITE6.P8(GND[102]) SITE6.P9(GND[103]) SITE6.P10(GND[104]) SITE6.P11(GND[105]) SITE6.P12(GND[106]) SITE6.P13(GND[107]) SITE6.P14(GND[108]) SITE6.P15(GND[109]) SITE6.P16(GND[110]) SITE6.P17(GND[111]) SITE6.P18(GND[112]) SITE6.R8(GND[113]) SITE6.R9(GND[114]) SITE6.R16(GND[116]) SITE6.R17(GND[117]) SITE6.R18(GND[118]) SITE6.T5(GND[119]) SITE6.T8(GND[120]) SITE6.T9(GND[121]) SITE6.T15(GND[122]) SITE6.T16(GND[123]) SITE6.T17(GND[124]) SITE6.T21(GND[125]) SITE6.U9(GND[126]) SITE6.U15(GND[127]) SITE6.U16(GND[128]) SITE8.B2(GND[0]) SITE8.B11(GND[1]) SITE8.B12(GND[2]) SITE8.B14(GND[3]) SITE8.B17(GND[4]) SITE8.B20(GND[5]) SITE8.C3(GND[6]) SITE8.C4(GND[7]) SITE8.C6(GND[8]) SITE8.C8(GND[9]) SITE8.C10(GND[10]) SITE8.C11(GND[11]) SITE8.C14(GND[12]) SITE8.C15(GND[13]) SITE8.C17(GND[14]) SITE8.D3(GND[15]) SITE8.E3(GND[16]) SITE8.E20(GND[17]) SITE8.F3(GND[18]) SITE8.F9(GND[19]) SITE8.F10(GND[20]) SITE8.F12(GND[21]) SITE8.F13(GND[22]) SITE8.G3(GND[23]) SITE8.G9(GND[24]) SITE8.G12(GND[25]) SITE8.G13(GND[26]) SITE8.G14(GND[27]) SITE8.G15(GND[28]) SITE8.G16(GND[29]) SITE8.G17(GND[30]) SITE8.H2(GND[31]) SITE8.H6(GND[33]) SITE8.H9(GND[34]) SITE8.H13(GND[35]) SITE8.H14(GND[36]) SITE8.H15(GND[37]) SITE8.H16(GND[38]) SITE8.H17(GND[39]) SITE8.J6(GND[40]) SITE8.J7(GND[41]) SITE8.J8(GND[42]) SITE8.J9(GND[43]) SITE8.J14(GND[44]) SITE8.J15(GND[45]) SITE8.J16(GND[46]) SITE8.J17(GND[47]) SITE8.J20(GND[48]) SITE8.J21(GND[49]) SITE8.K4(GND[51]) SITE8.K6(GND[52]) SITE8.K7(GND[53]) SITE8.K8(GND[54]) SITE8.K9(GND[55]) SITE8.K14(GND[56]) SITE8.K15(GND[57]) SITE8.K16(GND[58]) SITE8.K17(GND[59]) SITE8.L6(GND[60]) SITE8.L7(GND[61]) SITE8.L8(GND[62]) SITE8.L9(GND[63]) SITE8.L10(GND[64]) SITE8.L11(GND[65]) SITE8.L12(GND[66]) SITE8.L13(GND[67]) SITE8.L14(GND[68]) SITE8.L15(GND[69]) SITE8.L16(GND[70]) SITE8.L17(GND[71]) SITE8.L18(GND[72]) SITE8.L21(GND[73]) SITE8.M2(GND[74]) SITE8.M4(GND[75]) SITE8.M6(GND[76]) SITE8.M7(GND[77]) SITE8.M8(GND[78]) SITE8.M9(GND[79]) SITE8.M10(GND[80]) SITE8.M11(GND[81]) SITE8.M12(GND[82]) SITE8.M13(GND[83]) SITE8.M14(GND[84]) SITE8.M15(GND[85]) SITE8.M16(GND[86]) SITE8.M17(GND[87]) SITE8.N6(GND[89]) SITE8.N7(GND[90]) SITE8.N8(GND[91]) SITE8.N9(GND[92]) SITE8.N10(GND[93]) SITE8.N11(GND[94]) SITE8.N12(GND[95]) SITE8.N13(GND[96]) SITE8.N14(GND[97]) SITE8.N15(GND[98]) SITE8.N16(GND[99]) SITE8.N20(GND[100]) SITE8.P2(GND[101]) SITE8.P8(GND[102]) SITE8.P9(GND[103]) SITE8.P10(GND[104]) SITE8.P11(GND[105]) SITE8.P12(GND[106]) SITE8.P13(GND[107]) SITE8.P14(GND[108]) SITE8.P15(GND[109]) SITE8.P16(GND[110]) SITE8.P17(GND[111]) SITE8.P18(GND[112]) SITE8.R8(GND[113]) SITE8.R9(GND[114]) SITE8.R16(GND[116]) SITE8.R17(GND[117]) SITE8.R18(GND[118]) SITE8.T5(GND[119]) SITE8.T8(GND[120]) SITE8.T9(GND[121]) SITE8.T15(GND[122]) SITE8.T16(GND[123]) SITE8.T17(GND[124]) SITE8.T21(GND[125]) SITE8.U9(GND[126]) SITE8.U15(GND[127]) SITE8.U16(GND[128]) ; also on sheet 1 2 3 4 5 6 7 8 9 10 11 12 13 14 17 18 19 20 21 22 23 24 25 26 27 28 30 31 32 33 34 35
6SA_CBIT_R2: 6K2.8(V-)
6SA_CBIT_R3: 6K3.8(V-)
6SA_CBIT_R4: 6K4.8(V-)
6SA_CBIT_R5: 6K5.8(V-)
6SA_CBIT_R6: 6K6.8(V-)
6SA_CBIT_R7: 6K7.8(V-)
6SA_CBIT_R29: 6K29.8(V-)
6SA_CBIT_R32: 6K32.8(V-)
6SA_CBIT_R34: 6K34.8(V-)
6SA_CBIT_S01: 6R163.1
6SA_CBIT_S02: 6R164.1
6SA_CBIT_S03: 6R165.1
6SA_CBIT_S25: 6MK1.2(V-) 6MR12.2
6SA_CBIT_S26: 6MK2.2(V-) 6MR15.2
6SA_CBIT_S27: 6MK4.2(V-) 6MR17.2
6SA_CBIT_S28: 6MK3.2(V-)
6SA_CBIT_S97: 6R982.1
8SA_CBIT_R2: 8K2.8(V-)
8SA_CBIT_R3: 8K3.8(V-)
8SA_CBIT_R4: 8K4.8(V-)
8SA_CBIT_R5: 8K5.8(V-)
8SA_CBIT_R6: 8K6.8(V-)
8SA_CBIT_R7: 8K7.8(V-)
8SA_CBIT_R29: 8K29.8(V-)
8SA_CBIT_R32: 8K32.8(V-)
8SA_CBIT_R34: 8K34.8(V-)
8SA_CBIT_S01: 8R163.1
8SA_CBIT_S02: 8R164.1
8SA_CBIT_S03: 8R165.1
8SA_CBIT_S25: 8MK1.2(V-) 8MR12.2
8SA_CBIT_S26: 8MK2.2(V-) 8MR15.2
8SA_CBIT_S27: 8MK4.2(V-) 8MR17.2
8SA_CBIT_S28: 8MK3.2(V-)
8SA_CBIT_S97: 8R982.1
S6_0V5: 6C286.1 6C288.1 6MK1.4 6MR2.2 6MR3.1 6MR4.1 6MR5.1 6MR6.1 6MU3.3(+IN)
S6_0V25: 6MK4.3 6MR18.2 6MR19.1
S6_0V75: 6C290.1 6MK2.4 6MR10.2 6MU3.6(OUT)
S6_1SPI_CK: 6K2.7
S6_1SPI_DI: 6K4.7
S6_1SPI_DO: 6K4.2
S6_1SPI_HLD: 6K6.2
S6_1SPI_WPZ: 6K6.7
S6_3V3_USB2_MUX: 6BD21.2 6C262.1 6U31.4(VCC)
S6_3V3_XTAL32K: 6BD1728.2 6C1074.1 6R981.1 6U449.10(VCC)
S6_AWG_3SHARE+: 6K34.4 ; also on sheet 20
S6_B_DCH105: SITE6.C12(PAD_RTC_IO4)
S6_B_DCH106: SITE6.D13(PAD_RTC_IO5)
S6_DCH015: SITE6.N1(PAD_AUD_MICCM0)
S6_DCH016: SITE6.L1(PAD_AUD_MICCM1)
S6_DCH017: SITE6.L3(PAD_AUD_LINEOUT_RP)
S6_DCH018: SITE6.L4(PAD_AUD_LINEOUT_RN)
S6_DCH063: SITE6.A17(PAD_PM_SDIO_CLK)
S6_DCH064: SITE6.B16(PAD_PM_SDIO_CMD)
S6_DCH065: SITE6.A18(PAD_PM_SDIO_D0)
S6_DCH066: SITE6.B18(PAD_PM_SDIO_D1)
S6_DCH067: SITE6.B15(PAD_PM_SDIO_D2)
S6_DCH068: SITE6.A15(PAD_PM_SDIO_D3)
S6_DCH069: SITE6.B19(PAD_PM_SDIO_INT)
S6_DCH082: SITE6.D15(PAD_PM_FUART_CTS)
S6_DCH083: SITE6.D16(PAD_PM_FUART_RTS)
S6_DCH088: SITE6.G20(PAD_PM_PWM2)
S6_DCH089: SITE6.H20(PAD_PM_PWM3)
S6_DCH090: SITE6.A21(PAD_PM_SAR_GPIO1)
S6_DCH103: SITE6.E12(PAD_RTC_IO0)
S6_DCH104: SITE6.D12(PAD_RTC_IO1)
S6_DCH107: SITE6.E11(PAD_RESET)
S6_DCH108: 6K32.2
S6_DCH109: 6K32.7
S6_DCH110: 6U449.3(MHL+)
S6_DCH111: 6U449.4(MHL-)
S6_M_2V5: 6C284.1 6C285.1 6MR2.1 6MU2.6(VOUT)
S6_M_3V2: 6C282.1 6C283.1 6C289.1 6MR1.1 6MU1.5(Vout) 6MU2.2(VIN) 6MU3.7(V+)
S6_Mpdch01: SITE6.D7(PAD_I2C1_SDA)
S6_Mpdch03+: 6U31.2(D+)
S6_Mpdch03-: 6U31.3(D-)
S6_Mpdch05: SITE6.E7(PAD_I2C1_SCL)
S6_Mpdch06: SITE6.T4(PAD_SD0_D1)
S6_Mpdch09: SITE6.E8(PAD_SR_RST0)
S6_Mpdch10: SITE6.D8(PAD_SR_MCLK0)
S6_Mpdch11: SITE6.T3(PAD_SD0_CDZ)
S6_Mpdch13: SITE6.U4(PAD_SD0_D0)
S6_Mpdch14: SITE6.U5(PAD_SD0_CLK)
S6_Mpdch15: SITE6.T6(PAD_SD0_CMD)
S6_Mpdch16: SITE6.U7(PAD_SD0_D3)
S6_Mpdch17: SITE6.T7(PAD_SD0_D2)
S6_Mpdch18: SITE6.U20(PAD_FUART_RX)
S6_Mpdch19: SITE6.U21(PAD_FUART_TX)
S6_Mpdch20: SITE6.U18(PAD_FUART_RTS)
S6_Mpdch21: SITE6.R2(PAD_GPIO0)
S6_Mpdch22: SITE6.P6(PAD_GPIO5)
S6_Mpdch23: SITE6.R3(PAD_GPIO1)
S6_Mpdch24: SITE6.T2(PAD_GPIO10)
S6_Mpdch25: SITE6.R1(PAD_GPIO8)
S6_Mpdch26: SITE6.T1(PAD_GPIO9)
S6_Mpdch27: SITE6.P7(PAD_GPIO6)
S6_Mpdch28: SITE6.P4(PAD_GPIO3)
S6_Mpdch29: SITE6.U2(PAD_GPIO11)
S6_Mpdch30: SITE6.R7(PAD_GPIO7)
S6_Mpdch32: 6K2.2
S6_Mpdch33: SITE6.L2(PAD_AUD_MICIN1)
S6_Mpdch34: 6C264.1 SITE6.M3(PAD_AUD_VAG)
S6_Mpdch35: SITE6.N2(PAD_AUD_MICIN0)
S6_Mpdch36: SITE6.L20(PAD_I2C0_SDA)
S6_Mpdch49: SITE6.E5(PAD_SR_RST1)
S6_Mpdch50: SITE6.D5(PAD_SR_MCLK1)
S6_Mpdch51: SITE6.T18(PAD_FUART_CTS)
S6_Mpdch52: SITE6.T19(PAD_MSPI0_CZ)
S6_Mpdch53: SITE6.R4(PAD_GPIO2)
S6_Mpdch54: SITE6.P5(PAD_GPIO4)
S6_Mpdch55: SITE6.D4(PAD_I2C2_SCL)
S6_Mpdch56: SITE6.E4(PAD_I2C2_SDA)
S6_Mpdch57: SITE6.N19(PAD_MSPI0_CK)
S6_Mpdch58: SITE6.P19(PAD_MSPI0_DI)
S6_Mpdch59: SITE6.R19(PAD_MSPI0_DO)
S6_Mpdch60: SITE6.M20(PAD_I2C0_SCL)
S6_Mpdch61: SITE6.G21(PAD_PM_UART_RX)
S6_Mpdch62: SITE6.H22(PAD_PM_UART_TX)
S6_Mpdch63: SITE6.C19(PAD_PM_I2C_SDA)
S6_Mpdch64: SITE6.D19(PAD_PM_I2C_SCL)
S6_Mpdch65: SITE6.B22(PAD_PM_GPIO5)
S6_Mpdch66: SITE6.C22(PAD_PM_GPIO6)
S6_Mpdch68: SITE6.B21(PAD_PM_GPIO4)
S6_Mpdch69: SITE6.F19(PAD_PM_PWM1)
S6_Mpdch71: SITE6.H21(PAD_PM_GPIO11)
S6_Mpdch72: SITE6.E15(PAD_PM_FUART_RX)
S6_Mpdch73: SITE6.E18(PAD_PM_GPIO2)
S6_Mpdch74: SITE6.D18(PAD_PM_GPIO3)
S6_Mpdch75: SITE6.E22(PAD_PM_PSPI0_DO)
S6_Mpdch76: SITE6.F22(PAD_PM_PSPI0_DI)
S6_Mpdch77: SITE6.E19(PAD_PM_PWM0)
S6_Mpdch78: SITE6.C20(PAD_PM_UART2_RX)
S6_Mpdch79: SITE6.D20(PAD_PM_UART2_TX)
S6_Mpdch80: SITE6.E21(PAD_PM_PSPI0_CK)
S6_Mpdch81: SITE6.D21(PAD_PM_PSPI0_CZ)
S6_Mpdch84: SITE6.F21(PAD_PM_PSPI0_INT)
S6_Mpdch85: SITE6.E17(PAD_PM_GPIO1)
S6_Mpdch86: SITE6.C16(PAD_PM_GPIO0)
S6_Mpdch87: SITE6.E14(PAD_PM_FUART_TX)
S6_Mpdch88: 6K34.2
S6_MUX_3V3: 6BD21.1 6BD1728.1 6R512.1 ; also on sheet 5
S6_PM_SAR_GPIO0: 6K34.3 6MK3.4 S6_VREF_OUT.1(TP) SITE6.A20(PAD_PM_SAR_GPIO0)
S6_SPI_CK_ABCD_CASE: 6K2.6 SITE6.T22(PAD_SPI_CK)
S6_SPI_CK_B_CASE: 6K2.5 6K3.6
S6_SPI_CK_C_CASE: 6K3.7 6U18.7(RESET#)
S6_SPI_CK_D_CASE: 6K3.5 6U19.6
S6_SPI_CZ_ABCD_CASE: 6K2.3 SITE6.M21(PAD_SPI_CZ)
S6_SPI_CZ_B_CASE: 6K2.4 6K3.3
S6_SPI_CZ_C_CASE: 6K3.2 6R200.2 6U18.1(CS#)
S6_SPI_CZ_D_CASE: 6K3.4 6R205.2 6U19.1
S6_SPI_DI_ABCD_CASE: 6K4.6 SITE6.R21(PAD_SPI_DI)
S6_SPI_DI_B_CASE: 6K4.5 6K5.6
S6_SPI_DI_C_CASE: 6K5.7
S6_SPI_DI_D_CASE: 6K5.5 6U19.5
S6_SPI_DO_ABCD_CASE: 6K4.3 SITE6.P22(PAD_SPI_DO)
S6_SPI_DO_B_CASE: 6K4.4 6K5.3
S6_SPI_DO_C_CASE: 6K5.2
S6_SPI_DO_D_CASE: 6K5.4 6U19.2
S6_SPI_HLD_ABCD_CASE: 6K6.3 SITE6.P21(PAD_SPI_HLD)
S6_SPI_HLD_B_CASE: 6K6.4 6K7.3
S6_SPI_HLD_C_CASE: 6K7.2 6R202.1
S6_SPI_HLD_D_CASE: 6K7.4 6R206.1 6U19.7
S6_SPI_WPZ_ABCD_CASE: 6K6.6 SITE6.N21(PAD_SPI_WPZ)
S6_SPI_WPZ_B_CASE: 6K6.5 6K7.6
S6_SPI_WPZ_C_CASE: 6K7.7 6R203.2 6U18.2(SO)
S6_SPI_WPZ_D_CASE: 6K7.5 6R207.2 6U19.3
S6_USB2_SEL0: 6R164.2 6U31.6(SEL0)
S6_USB2_SEL1: 6R163.2 6U31.5(SEL1)
S6_USB2_SELS: 6R165.2 6U31.16(SELS)
S6_USB_D_AB_CASE+: 6U31.10(HSD2+) SITE6.J3(PAD_DP_USB)
S6_USB_D_AB_CASE-: 6U31.9(HSD2-) SITE6.J2(PAD_DM_USB)
S6_USB_D_B_CASE+: 6R160.2 6U31.8(HSD2S+)
S6_USB_D_B_CASE-: 6R161.2 6U31.7(HSD2S-)
S6_USER_3V3: 6C334.1 6C335.1 6C336.2 6C337.2 6C338.2 6C339.2 6R200.1 6R201.2 6R202.2 6R203.1 6R204.2 6R205.1 6R206.2 6R207.1 6U17.3(Vout) S6_USER_3V3.1
S6_XTAL_24M_IN_ABC_CASE: 6K32.3 SITE6.L22(PAD_XTAL_IN_24M)
S6_XTAL_24M_IN_B_CASE: 6K32.4 6R135.1
S6_XTAL_24M_IN_C_CASE: 6C267.1 6R135.2 6R136.2 6Y1.3
S6_XTAL_24M_OUT_ABC_CASE: 6K32.6 SITE6.K21(PAD_XTAL_OUT_24M)
S6_XTAL_24M_OUT_B_CASE: 6K32.5 6R137.1
S6_XTAL_24M_OUT_C_CASE: 6C268.1 6R136.1 6R137.2 6Y1.1
S6_XTAL_IN_32K_A_CASE: 6K29.7 6U449.7(D-)
S6_XTAL_IN_32K_ABCD_CASE: 6K29.6 SITE6.B13(PAD_XTAL_IN_32K)
S6_XTAL_IN_32K_B_CASE: 6C271.1 6K29.5 6Y2.1
S6_XTAL_IN_32K_D_CASE: 6R923.1 6R973.2 6U449.2(USB-)
S6_XTAL_OUT_32K_A_CASE: 6K29.2 6U449.8(D+)
S6_XTAL_OUT_32K_ABCD_CASE: 6K29.3 SITE6.A12(PAD_XTAL_OUT_32K)
S6_XTAL_OUT_32K_B_CASE: 6C272.1 6K29.4 6Y2.2
S6_XTAL_OUT_32K_D_CASE: 6R652.1 6R973.1 6U449.1(USB+)
S8_0V5: 8C286.1 8C288.1 8MK1.4 8MR2.2 8MR3.1 8MR4.1 8MR5.1 8MR6.1 8MU3.3(+IN)
S8_0V25: 8MK4.3 8MR18.2 8MR19.1
S8_0V75: 8C290.1 8MK2.4 8MR10.2 8MU3.6(OUT)
S8_1SPI_CK: 8K2.7
S8_1SPI_DI: 8K4.7
S8_1SPI_DO: 8K4.2
S8_1SPI_HLD: 8K6.2
S8_1SPI_WPZ: 8K6.7
S8_3V3_USB2_MUX: 8BD21.2 8C262.1 8U31.4(VCC)
S8_3V3_XTAL32K: 8BD1728.2 8C1074.1 8R981.1 8U449.10(VCC)
S8_AWG_3SHARE+: 8K34.4 ; also on sheet 20
S8_B_DCH105: SITE8.C12(PAD_RTC_IO4)
S8_B_DCH106: SITE8.D13(PAD_RTC_IO5)
S8_DCH015: SITE8.N1(PAD_AUD_MICCM0)
S8_DCH016: SITE8.L1(PAD_AUD_MICCM1)
S8_DCH017: SITE8.L3(PAD_AUD_LINEOUT_RP)
S8_DCH018: SITE8.L4(PAD_AUD_LINEOUT_RN)
S8_DCH063: SITE8.A17(PAD_PM_SDIO_CLK)
S8_DCH064: SITE8.B16(PAD_PM_SDIO_CMD)
S8_DCH065: SITE8.A18(PAD_PM_SDIO_D0)
S8_DCH066: SITE8.B18(PAD_PM_SDIO_D1)
S8_DCH067: SITE8.B15(PAD_PM_SDIO_D2)
S8_DCH068: SITE8.A15(PAD_PM_SDIO_D3)
S8_DCH069: SITE8.B19(PAD_PM_SDIO_INT)
S8_DCH082: SITE8.D15(PAD_PM_FUART_CTS)
S8_DCH083: SITE8.D16(PAD_PM_FUART_RTS)
S8_DCH088: SITE8.G20(PAD_PM_PWM2)
S8_DCH089: SITE8.H20(PAD_PM_PWM3)
S8_DCH090: SITE8.A21(PAD_PM_SAR_GPIO1)
S8_DCH103: SITE8.E12(PAD_RTC_IO0)
S8_DCH104: SITE8.D12(PAD_RTC_IO1)
S8_DCH107: SITE8.E11(PAD_RESET)
S8_DCH108: 8K32.2
S8_DCH109: 8K32.7
S8_DCH110: 8U449.3(MHL+)
S8_DCH111: 8U449.4(MHL-)
S8_M_2V5: 8C284.1 8C285.1 8MR2.1 8MU2.6(VOUT)
S8_M_3V2: 8C282.1 8C283.1 8C289.1 8MR1.1 8MU1.5(Vout) 8MU2.2(VIN) 8MU3.7(V+)
S8_Mpdch01: SITE8.D7(PAD_I2C1_SDA)
S8_Mpdch03+: 8U31.2(D+)
S8_Mpdch03-: 8U31.3(D-)
S8_Mpdch05: SITE8.E7(PAD_I2C1_SCL)
S8_Mpdch06: SITE8.T4(PAD_SD0_D1)
S8_Mpdch09: SITE8.E8(PAD_SR_RST0)
S8_Mpdch10: SITE8.D8(PAD_SR_MCLK0)
S8_Mpdch11: SITE8.T3(PAD_SD0_CDZ)
S8_Mpdch13: SITE8.U4(PAD_SD0_D0)
S8_Mpdch14: SITE8.U5(PAD_SD0_CLK)
S8_Mpdch15: SITE8.T6(PAD_SD0_CMD)
S8_Mpdch16: SITE8.U7(PAD_SD0_D3)
S8_Mpdch17: SITE8.T7(PAD_SD0_D2)
S8_Mpdch18: SITE8.U20(PAD_FUART_RX)
S8_Mpdch19: SITE8.U21(PAD_FUART_TX)
S8_Mpdch20: SITE8.U18(PAD_FUART_RTS)
S8_Mpdch21: SITE8.R2(PAD_GPIO0)
S8_Mpdch22: SITE8.P6(PAD_GPIO5)
S8_Mpdch23: SITE8.R3(PAD_GPIO1)
S8_Mpdch24: SITE8.T2(PAD_GPIO10)
S8_Mpdch25: SITE8.R1(PAD_GPIO8)
S8_Mpdch26: SITE8.T1(PAD_GPIO9)
S8_Mpdch27: SITE8.P7(PAD_GPIO6)
S8_Mpdch28: SITE8.P4(PAD_GPIO3)
S8_Mpdch29: SITE8.U2(PAD_GPIO11)
S8_Mpdch30: SITE8.R7(PAD_GPIO7)
S8_Mpdch32: 8K2.2
S8_Mpdch33: SITE8.L2(PAD_AUD_MICIN1)
S8_Mpdch34: 8C264.1 SITE8.M3(PAD_AUD_VAG)
S8_Mpdch35: SITE8.N2(PAD_AUD_MICIN0)
S8_Mpdch36: SITE8.L20(PAD_I2C0_SDA)
S8_Mpdch49: SITE8.E5(PAD_SR_RST1)
S8_Mpdch50: SITE8.D5(PAD_SR_MCLK1)
S8_Mpdch51: SITE8.T18(PAD_FUART_CTS)
S8_Mpdch52: SITE8.T19(PAD_MSPI0_CZ)
S8_Mpdch53: SITE8.R4(PAD_GPIO2)
S8_Mpdch54: SITE8.P5(PAD_GPIO4)
S8_Mpdch55: SITE8.D4(PAD_I2C2_SCL)
S8_Mpdch56: SITE8.E4(PAD_I2C2_SDA)
S8_Mpdch57: SITE8.N19(PAD_MSPI0_CK)
S8_Mpdch58: SITE8.P19(PAD_MSPI0_DI)
S8_Mpdch59: SITE8.R19(PAD_MSPI0_DO)
S8_Mpdch60: SITE8.M20(PAD_I2C0_SCL)
S8_Mpdch61: SITE8.G21(PAD_PM_UART_RX)
S8_Mpdch62: SITE8.H22(PAD_PM_UART_TX)
S8_Mpdch63: SITE8.C19(PAD_PM_I2C_SDA)
S8_Mpdch64: SITE8.D19(PAD_PM_I2C_SCL)
S8_Mpdch65: SITE8.B22(PAD_PM_GPIO5)
S8_Mpdch66: SITE8.C22(PAD_PM_GPIO6)
S8_Mpdch68: SITE8.B21(PAD_PM_GPIO4)
S8_Mpdch69: SITE8.F19(PAD_PM_PWM1)
S8_Mpdch71: SITE8.H21(PAD_PM_GPIO11)
S8_Mpdch72: SITE8.E15(PAD_PM_FUART_RX)
S8_Mpdch73: SITE8.E18(PAD_PM_GPIO2)
S8_Mpdch74: SITE8.D18(PAD_PM_GPIO3)
S8_Mpdch75: SITE8.E22(PAD_PM_PSPI0_DO)
S8_Mpdch76: SITE8.F22(PAD_PM_PSPI0_DI)
S8_Mpdch77: SITE8.E19(PAD_PM_PWM0)
S8_Mpdch78: SITE8.C20(PAD_PM_UART2_RX)
S8_Mpdch79: SITE8.D20(PAD_PM_UART2_TX)
S8_Mpdch80: SITE8.E21(PAD_PM_PSPI0_CK)
S8_Mpdch81: SITE8.D21(PAD_PM_PSPI0_CZ)
S8_Mpdch84: SITE8.F21(PAD_PM_PSPI0_INT)
S8_Mpdch85: SITE8.E17(PAD_PM_GPIO1)
S8_Mpdch86: SITE8.C16(PAD_PM_GPIO0)
S8_Mpdch87: SITE8.E14(PAD_PM_FUART_TX)
S8_Mpdch88: 8K34.2
S8_MUX_3V3: 8BD21.1 8BD1728.1 8R512.1 ; also on sheet 1
S8_PM_SAR_GPIO0: 8K34.3 8MK3.4 S8_VREF_OUT.1(TP) SITE8.A20(PAD_PM_SAR_GPIO0)
S8_SPI_CK_ABCD_CASE: 8K2.6 SITE8.T22(PAD_SPI_CK)
S8_SPI_CK_B_CASE: 8K2.5 8K3.6
S8_SPI_CK_C_CASE: 8K3.7 8U18.7(RESET#)
S8_SPI_CK_D_CASE: 8K3.5 8U19.6
S8_SPI_CZ_ABCD_CASE: 8K2.3 SITE8.M21(PAD_SPI_CZ)
S8_SPI_CZ_B_CASE: 8K2.4 8K3.3
S8_SPI_CZ_C_CASE: 8K3.2 8R200.2 8U18.1(CS#)
S8_SPI_CZ_D_CASE: 8K3.4 8R205.2 8U19.1
S8_SPI_DI_ABCD_CASE: 8K4.6 SITE8.R21(PAD_SPI_DI)
S8_SPI_DI_B_CASE: 8K4.5 8K5.6
S8_SPI_DI_C_CASE: 8K5.7
S8_SPI_DI_D_CASE: 8K5.5 8U19.5
S8_SPI_DO_ABCD_CASE: 8K4.3 SITE8.P22(PAD_SPI_DO)
S8_SPI_DO_B_CASE: 8K4.4 8K5.3
S8_SPI_DO_C_CASE: 8K5.2
S8_SPI_DO_D_CASE: 8K5.4 8U19.2
S8_SPI_HLD_ABCD_CASE: 8K6.3 SITE8.P21(PAD_SPI_HLD)
S8_SPI_HLD_B_CASE: 8K6.4 8K7.3
S8_SPI_HLD_C_CASE: 8K7.2 8R202.1
S8_SPI_HLD_D_CASE: 8K7.4 8R206.1 8U19.7
S8_SPI_WPZ_ABCD_CASE: 8K6.6 SITE8.N21(PAD_SPI_WPZ)
S8_SPI_WPZ_B_CASE: 8K6.5 8K7.6
S8_SPI_WPZ_C_CASE: 8K7.7 8R203.2 8U18.2(SO)
S8_SPI_WPZ_D_CASE: 8K7.5 8R207.2 8U19.3
S8_USB2_SEL0: 8R164.2 8U31.6(SEL0)
S8_USB2_SEL1: 8R163.2 8U31.5(SEL1)
S8_USB2_SELS: 8R165.2 8U31.16(SELS)
S8_USB_D_AB_CASE+: 8U31.10(HSD2+) SITE8.J3(PAD_DP_USB)
S8_USB_D_AB_CASE-: 8U31.9(HSD2-) SITE8.J2(PAD_DM_USB)
S8_USB_D_B_CASE+: 8R160.2 8U31.8(HSD2S+)
S8_USB_D_B_CASE-: 8R161.2 8U31.7(HSD2S-)
S8_USER_3V3: 8C334.1 8C335.1 8C336.2 8C337.2 8C338.2 8C339.2 8R200.1 8R201.2 8R202.2 8R203.1 8R204.2 8R205.1 8R206.2 8R207.1 8U17.3(Vout) S8_USER_3V3.1
S8_XTAL_24M_IN_ABC_CASE: 8K32.3 SITE8.L22(PAD_XTAL_IN_24M)
S8_XTAL_24M_IN_B_CASE: 8K32.4 8R135.1
S8_XTAL_24M_IN_C_CASE: 8C267.1 8R135.2 8R136.2 8Y1.3
S8_XTAL_24M_OUT_ABC_CASE: 8K32.6 SITE8.K21(PAD_XTAL_OUT_24M)
S8_XTAL_24M_OUT_B_CASE: 8K32.5 8R137.1
S8_XTAL_24M_OUT_C_CASE: 8C268.1 8R136.1 8R137.2 8Y1.1
S8_XTAL_IN_32K_A_CASE: 8K29.7 8U449.7(D-)
S8_XTAL_IN_32K_ABCD_CASE: 8K29.6 SITE8.B13(PAD_XTAL_IN_32K)
S8_XTAL_IN_32K_B_CASE: 8C271.1 8K29.5 8Y2.1
S8_XTAL_IN_32K_D_CASE: 8R923.1 8R973.2 8U449.2(USB-)
S8_XTAL_OUT_32K_A_CASE: 8K29.2 8U449.8(D+)
S8_XTAL_OUT_32K_ABCD_CASE: 8K29.3 SITE8.A12(PAD_XTAL_OUT_32K)
S8_XTAL_OUT_32K_B_CASE: 8C272.1 8K29.4 8Y2.2
S8_XTAL_OUT_32K_D_CASE: 8R652.1 8R973.1 8U449.1(USB+)
UT1_UP5V: 6C278.1 6C279.1 6C280.1 6C281.1 6C332.1 6C333.1 6C476.1 6C477.1 6C478.1 6K2.1(V+) 6K3.1(V+) 6K4.1(V+) 6K5.1(V+) 6K6.1(V+) 6K7.1(V+) 6K29.1(V+) 6K32.1(V+) 6K34.1(V+) 6MBD1.1 6MR11.1 6MR12.1 6MR13.1 6MR14.2 6MR15.1 6MR16.1 6MR17.1 6MU1.1(Vin) 6MU1.3(EN) 6R331.1 6R509.2 6U17.2(Vin) 6U108.4(VDD) 8C278.1 8C279.1 8C280.1 8C281.1 8C332.1 8C333.1 8C476.1 8C477.1 8C478.1 8K2.1(V+) 8K3.1(V+) 8K4.1(V+) 8K5.1(V+) 8K6.1(V+) 8K7.1(V+) 8K29.1(V+) 8K32.1(V+) 8K34.1(V+) 8MBD1.1 8MR11.1 8MR12.1 8MR13.1 8MR14.2 8MR15.1 8MR16.1 8MR17.1 8MU1.1(Vin) 8MU1.3(EN) 8R331.1 8R509.2 8U17.2(Vin) 8U108.4(VDD) ; also on sheet 2 4 6 8 10 12 14 17 19 20 21 22 23 24 25 26 27 28 30 31 32 33 34 35
N22589852: 6R162.1 6U31.15(OE#)
N22589877: 6R510.2 6R511.1 6U108.1(ADJ)
N22589883: 6C475.1 6R510.1 6R512.2 6TP_MUX_3V3.1(TP) 6U108.5(VOUT)
N22589884: 6R509.1 6U108.3(CE)
N22590180: 6BD9.1 SITE6.N3(PAD_AUD_VRM)
N22590184: 6MU4.3(EN) 6R331.2
N22590218: 6C299.2 6MU4.1(FILTER)
N22590219: 6C300.1 6C301.1 6MR18.1 6MU4.5(OUTS) 6MU4.6(OUTF)
N22590224: 6C298.2 6MBD1.2 6MU4.4(IN)
N22590253: 6MR1.2 6MR7.2 6MU1.4(FB)
N22590263: 6MR8.1 6MR9.1 6MU3.2(-IN)
N22590300: 6MK2.1(V+) 6MR13.2
N22590305: 6MK1.3 6MK2.3 6MK3.3 6MK4.4
N22590312: 6MK3.1(V+) 6MR14.1
N22590316: 6MK4.1(V+) 6MR16.2
N22590337: 6MR9.2 6MR10.1
N22590338: 6MK1.1(V+) 6MR11.2
N22590506: 6R980.1 6U449.6(OE#)
N22590517: 6R981.2 6R982.2 6U449.9(SEL)
N22590639: 6R204.1 6U19.8
N22590659: 6R201.1 6U18.8(VCC)
N22605576: 8R162.1 8U31.15(OE#)
N22605601: 8R510.2 8R511.1 8U108.1(ADJ)
N22605607: 8C475.1 8R510.1 8R512.2 8TP_MUX_3V3.1(TP) 8U108.5(VOUT)
N22605608: 8R509.1 8U108.3(CE)
N22605904: 8BD9.1 SITE8.N3(PAD_AUD_VRM)
N22605908: 8MU4.3(EN) 8R331.2
N22605942: 8C299.2 8MU4.1(FILTER)
N22605943: 8C300.1 8C301.1 8MR18.1 8MU4.5(OUTS) 8MU4.6(OUTF)
N22605948: 8C298.2 8MBD1.2 8MU4.4(IN)
N22605977: 8MR1.2 8MR7.2 8MU1.4(FB)
N22605987: 8MR8.1 8MR9.1 8MU3.2(-IN)
N22606024: 8MK2.1(V+) 8MR13.2
N22606029: 8MK1.3 8MK2.3 8MK3.3 8MK4.4
N22606036: 8MK3.1(V+) 8MR14.1
N22606040: 8MK4.1(V+) 8MR16.2
N22606061: 8MR9.2 8MR10.1
N22606062: 8MK1.1(V+) 8MR11.2
N22606230: 8R980.1 8U449.6(OE#)
N22606241: 8R981.2 8R982.2 8U449.9(SEL)
N22606363: 8R204.1 8U19.8
N22606383: 8R201.1 8U18.8(VCC)

Not connected (* = marked no-connect by the designer): 6K34 5* 6* 7*; 6MU2 1(NC1)* 3(NC2)* 5(NC3)* 7(NC4)* 8(TP)*; 6MU3 1(NC1)* 5(NC2)* 8(NC3)*; 6U18 3(WP#) 4(GND) 5(SI) 6(SCLK); 6U19 GH1* GH2*; 6U31 11(HSD1+)* 12(HSD1-)* 13(HSD0+)* 14(HSD0-)*; 8K34 5* 6* 7*; 8MU2 1(NC1)* 3(NC2)* 5(NC3)* 7(NC4)* 8(TP)*; 8MU3 1(NC1)* 5(NC2)* 8(NC3)*; 8U18 3(WP#) 4(GND) 5(SI) 6(SCLK); 8U19 GH1* GH2*; 8U31 11(HSD1+)* 12(HSD1-)* 13(HSD0+)* 14(HSD0-)*; SITE6 A1(NC[0])* A3(NC[1])* A5(NC[2])* A7(NC[3])* A9(NC[4])* A11(NC[5])* A13(NC[6])* A14(NC[7])* A16(NC[8])* A19(NC[9])* A22(NC[10])* C5(NC[11])* C7(NC[12])* C9(NC[13])* C13(NC[14])* C18(NC[15])* C21(NC[16])* D1(NC[17])* D6(NC[18])* D9(NC[19])* D10(NC[20])* D11(NC[21])* D14(NC[22])* D17(NC[23])* D22(NC[24])* E6(NC[25])* E9(NC[26])* E13(NC[27])* E16(NC[28])* F1(NC[29])* F5(NC[30])* F11(NC[31])* F14(NC[32])* F16(NC[33])* F18(NC[34])* F20(NC[35])* G4(NC[36])* G19(NC[37])* G22(NC[38])* H1(NC[39])* H3(NC[40])* H5(NC[41])* H18(NC[42])* J1(NC[43])* J4(NC[44])* J19(NC[45])* J22(NC[46])* K1(NC[47])* K2(NC[48])* K3(NC[49])* K5(NC[50])* K18(NC[51])* K20(NC[52])* K22(NC[53])* L19(NC[54])* M1(NC[55])* M5(NC[56])* M19(NC[57])* M22(NC[58])* N4(NC[59])* N5(NC[60])* N18(NC[61])* N22(NC[62])* NGH1* NGH2* NGH3* NGH4* NUT1* NUT2* NUT3* NUT4* P1(NC[63])* P20(NC[64])* R5(NC[65])* R6(NC[66])* R10(NC[67])* R12(NC[68])* R13(NC[69])* R20(NC[70])* R22(NC[71])* T12(NC[72])* T20(NC[73])* U1(NC[74])* U3(NC[75])* U6(NC[76])* U8(NC[77])* U10(NC[78])* U12(NC[79])* U14(NC[80])* U17(NC[81])* U19(NC[82])* U22(NC[83])*; SITE8 A1(NC[0])* A3(NC[1])* A5(NC[2])* A7(NC[3])* A9(NC[4])* A11(NC[5])* A13(NC[6])* A14(NC[7])* A16(NC[8])* A19(NC[9])* A22(NC[10])* C5(NC[11])* C7(NC[12])* C9(NC[13])* C13(NC[14])* C18(NC[15])* C21(NC[16])* D1(NC[17])* D6(NC[18])* D9(NC[19])* D10(NC[20])* D11(NC[21])* D14(NC[22])* D17(NC[23])* D22(NC[24])* E6(NC[25])* E9(NC[26])* E13(NC[27])* E16(NC[28])* F1(NC[29])* F5(NC[30])* F11(NC[31])* F14(NC[32])* F16(NC[33])* F18(NC[34])* F20(NC[35])* G4(NC[36])* G19(NC[37])* G22(NC[38])* H1(NC[39])* H3(NC[40])* H5(NC[41])* H18(NC[42])* J1(NC[43])* J4(NC[44])* J19(NC[45])* J22(NC[46])* K1(NC[47])* K2(NC[48])* K3(NC[49])* K5(NC[50])* K18(NC[51])* K20(NC[52])* K22(NC[53])* L19(NC[54])* M1(NC[55])* M5(NC[56])* M19(NC[57])* M22(NC[58])* N4(NC[59])* N5(NC[60])* N18(NC[61])* N22(NC[62])* NGH1* NGH2* NGH3* NGH4* NUT1* NUT2* NUT3* NUT4* P1(NC[63])* P20(NC[64])* R5(NC[65])* R6(NC[66])* R10(NC[67])* R12(NC[68])* R13(NC[69])* R20(NC[70])* R22(NC[71])* T12(NC[72])* T20(NC[73])* U1(NC[74])* U3(NC[75])* U6(NC[76])* U8(NC[77])* U10(NC[78])* U12(NC[79])* U14(NC[80])* U17(NC[81])* U19(NC[82])* U22(NC[83])*

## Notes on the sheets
sheet 36
- USB 2.0
- Close to DUT
- USB¡BAUD
- DIFF 90 ohm
- 3.3V
- XTAL
- PAD_RTC_IO4~5: Use wider traces.
- XTAL_24M
- USB DC MUX:
- Close to DUT
- FSUSB73UMX-UMLP16
  RON (Typical): 6.5 £[
- SEL1
- SEL0
- Function
- (mUbit7)
- (mUbit8)
- 0
- 1
- NA
- 1
- 0
- NA
- 1
- 1
- USB DC(default)
- Trace Width: 20 mil
- Close to DUT
- SELS
- Function
- XTAL_32K
- (mUbit9)
- 1
- R_ON(default)
- Close to DUT
- 0
- R_OFF
- Close to DUT
- Connect the bead directly to GND.
- apply GND shielding.
- PAD_PM_GPIO3~5: Use wider traces
- GND
- SPI FLASH
- FLASH
- NOR
- NAND
- CS#
- VCC
- 8
- DO/IO1
- HOLD#/RST#IO3
- WP#/IO2
- SCLK
- GND
- DI/IO0
- 4
- 5
- NOR¡GW25Q128JVSIQ-SOIC8
  NAND¡GW25N01GVZEIG
- Please measure the output voltage before shipment.
  (1)0.25V +/-1% (0.2475~0.2525V)
  (2)0.5V +/-1% (0.495~0.505V)
  (3)0.75V +/-1% (0.7425~0.7575V)
- SAR_GPIO0: Precise voltage levels of 0.25 V / 0.5 V / 0.75 V.
- Vout=0.5*(1+499/1K)=0.7495V
- NO
- NO
- NC
- supply current 0.235mA
- VOUT = 3 V (fixed by part number). Max. output current: ¡Ó10 mA.
- High-precision 0.25 V reference voltage source (V0 = 3 V ¡Ñ [1K / 12K] = 0.25 V).
- Relay (CH, AWG, SAR_GPIO0): Provide precision voltage levels of 0.25 V / 0.5 V / 0.75 V.
- Connect the precision voltage source before the relay.
- MCB Assign: Only channels A¡VD are allowed.
  Channels can be interchanged.
- AWG
- Use copper shapes for all connections from DUT to MK3.
  Ensure consistency across all SITES.
- Relay~ AWG Apply GND shielding.
sheet 37
- USB 2.0
- Close to DUT
- USB¡BAUD
- DIFF 90 ohm
- 3.3V
- XTAL
- PAD_RTC_IO4~5: Use wider traces.
- XTAL_24M
- USB DC MUX:
- Close to DUT
- FSUSB73UMX-UMLP16
  RON (Typical): 6.5 £[
- SEL1
- SEL0
- Function
- (mUbit7)
- (mUbit8)
- 0
- 1
- NA
- 1
- 0
- NA
- 1
- 1
- USB DC(default)
- Trace Width: 20 mil
- Close to DUT
- SELS
- Function
- XTAL_32K
- (mUbit9)
- 1
- R_ON(default)
- Close to DUT
- 0
- R_OFF
- Close to DUT
- Connect the bead directly to GND.
- apply GND shielding.
- PAD_PM_GPIO3~5: Use wider traces
- GND
- SPI FLASH
- FLASH
- NOR
- NAND
- CS#
- VCC
- 8
- DO/IO1
- HOLD#/RST#IO3
- WP#/IO2
- SCLK
- GND
- DI/IO0
- 4
- 5
- NOR¡GW25Q128JVSIQ-SOIC8
  NAND¡GW25N01GVZEIG
- Please measure the output voltage before shipment.
  (1)0.25V +/-1% (0.2475~0.2525V)
  (2)0.5V +/-1% (0.495~0.505V)
  (3)0.75V +/-1% (0.7425~0.7575V)
- SAR_GPIO0: Precise voltage levels of 0.25 V / 0.5 V / 0.75 V.
- Vout=0.5*(1+499/1K)=0.7495V
- NO
- NO
- NC
- supply current 0.235mA
- VOUT = 3 V (fixed by part number). Max. output current: ¡Ó10 mA.
- High-precision 0.25 V reference voltage source (V0 = 3 V ¡Ñ [1K / 12K] = 0.25 V).
- Relay (CH, AWG, SAR_GPIO0): Provide precision voltage levels of 0.25 V / 0.5 V / 0.75 V.
- Connect the precision voltage source before the relay.
- MCB Assign: Only channels A¡VD are allowed.
  Channels can be interchanged.
- AWG
- Use copper shapes for all connections from DUT to MK3.
  Ensure consistency across all SITES.
- Relay~ AWG Apply GND shielding.
